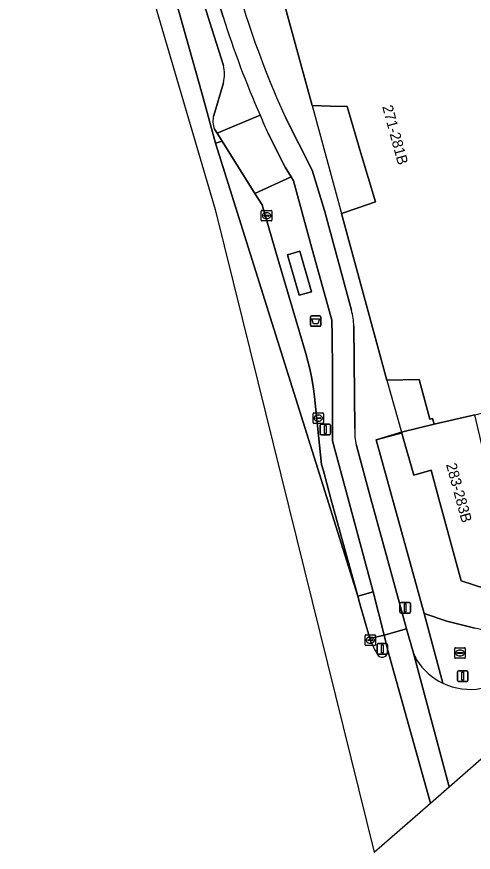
# Model space of a CAD drawing. Extents: x 162344 to 162869, y 381217 to 381818.
# Drawn here: x 162507.7 to 162551, y 381216.5 to 381295.7 of the extents above; entities that cross this region are included whole.
import ezdxf

# ---------------------------------------------------------------- set-up
doc = ezdxf.new("R2010")
doc.units = 0
for name, color, linetype in [('IMGEO_Afvalbak', 7, 'Continuous'), ('IMGEO_Berm_open', 7, 'Continuous'), ('IMGEO_Brandkraan', 7, 'Continuous'), ('IMGEO_Erf', 7, 'Continuous'), ('IMGEO_Fietspad_gesloten', 7, 'Continuous'), ('IMGEO_Fietspad_open', 7, 'Continuous'), ('IMGEO_Kolk', 7, 'Continuous'), ('IMGEO_Lichtmast', 7, 'Continuous'), ('IMGEO_Muur', 7, 'Continuous'), ('IMGEO_OVBaan_gesloten', 7, 'Continuous'), ('IMGEO_Pand', 7, 'Continuous'), ('IMGEO_Pand_nummerreeks', 7, 'Continuous'), ('IMGEO_Pand_overbouw', 7, 'Continuous'), ('IMGEO_Parkeervlak_open', 7, 'Continuous'), ('IMGEO_Rijbaan_lokaal_gesloten', 7, 'Continuous'), ('IMGEO_Rijbaan_regionaal_gesloten', 7, 'Continuous'), ('IMGEO_Verkeerseiland_open', 7, 'Continuous'), ('IMGEO_Verkeersregelinstallatiepaal', 7, 'Continuous'), ('IMGEO_Voetpad_gesloten', 7, 'Continuous'), ('IMGEO_Voetpad_open', 7, 'Continuous')]:
    doc.layers.add(name, color=color, linetype=linetype)

msp = doc.modelspace()

# ---------------------------------------------------------------- linework, layer by layer
at = {"layer": 'IMGEO_Afvalbak'}
for p, q in [((162535.561, 381266.45), (162535.561, 381267.25)), ((162535.561, 381267.25), (162535.561, 381266.45)), ((162535.661, 381267.35), (162536.451, 381267.35)), ((162536.451, 381267.35), (162535.661, 381267.35)), ((162536.551, 381267.25), (162536.551, 381266.45)), ((162536.551, 381266.45), (162536.551, 381267.25)), ((162536.451, 381266.35), (162535.661, 381266.35)), ((162535.661, 381266.35), (162536.451, 381266.35))]:
    msp.add_line(p, q, dxfattribs=at)
msp.add_lwpolyline([(162535.704, 381267.064), (162536.408, 381267.064), (162536.259, 381266.594), (162535.853, 381266.594), (162535.704, 381267.064)], dxfattribs=at)
for centre, start, end in [((162535.661, 381267.25), 90, 180), ((162535.661, 381267.25), 90, 180), ((162536.451, 381267.25), 0, 90), ((162536.451, 381267.25), 360, 90), ((162535.661, 381266.45), 180, 270), ((162535.661, 381266.45), 180, 270), ((162536.451, 381266.45), 270, 0), ((162536.451, 381266.45), 270, 0)]:
    msp.add_arc(centre, 0.1, start, end, dxfattribs=at)
at = {"layer": 'IMGEO_Berm_open'}
for points in [[(162510.574, 381341.66), (162511.386, 381341.368), (162511.659, 381341.199), (162511.867, 381340.946), (162512.219, 381340.273), (162517.818, 381322.123), (162520.103, 381314.39), (162520.562, 381312.814), (162522.874, 381305.299), (162525.989, 381295.243), (162527.307, 381291.065)], [(162527.279, 381295.674), (162524.133, 381305.697), (162521.857, 381313.223), (162521.427, 381314.724)], [(162527.313, 381289.434), (162526.386, 381286.339)], [(162526.464, 381285.037), (162526.715, 381284.645), (162530.786, 381286.346)], [(162530.786, 381286.346), (162526.715, 381284.645), (162527.18, 381283.901), (162530.281, 381278.934), (162533.735, 381280.515), (162533.169, 381281.443), (162531.534, 381284.676)]]:
    msp.add_lwpolyline(points, dxfattribs=at)
for points in [[(162537.654, 381255.503), (162537.645, 381262.173), (162537.64, 381265.461), (162537.595, 381266.931), (162535.6, 381274.097), (162533.967, 381280.135), (162533.735, 381280.515), (162530.281, 381278.934), (162530.988, 381277.853), (162532.465, 381272.733), (162535.121, 381263.759), (162535.505, 381262.307), (162535.632, 381261.729), (162535.653, 381261.609), (162535.857, 381260.414), (162535.952, 381259.66), (162536.619, 381253.257), (162536.79, 381252.665), (162537.51, 381250), (162538.37, 381246.814), (162540.052, 381240.792), (162541.522, 381241.189), (162539.141, 381250)], [(162534.488, 381269.288), (162533.382, 381273.13), (162534.57, 381273.472), (162535.675, 381269.629)]]:
    msp.add_lwpolyline(points, close=True, dxfattribs=at)
for centre, radius, start, end in [((162618.741, 381324.737), 95.969, 197.62834, 203.58065), ((162524.395, 381290.239), 3.027, 344.58062, 15.84093), ((162528.312, 381285.801), 2, 164.39587, 202.46086), ((162616.65, 381323.802), 93.678, 203.5682, 204.68741)]:
    msp.add_arc(centre, radius, start, end, dxfattribs=at)
at = {"layer": 'IMGEO_Brandkraan'}
for p, q in [((162549.25, 381234.966), (162549.25, 381235.818)), ((162549.325, 381235.892), (162550.177, 381235.892)), ((162549.509, 381235.386), (162549.509, 381235.398)), ((162549.947, 381235.349), (162549.549, 381235.349)), ((162549.552, 381235.435), (162549.95, 381235.435)), ((162549.738, 381235.672), (162549.763, 381235.672)), ((162549.993, 381235.398), (162549.993, 381235.386)), ((162550.251, 381235.818), (162550.251, 381234.966)), ((162550.177, 381234.892), (162549.325, 381234.892)), ((162549.761, 381235.112), (162549.736, 381235.112))]:
    msp.add_line(p, q, dxfattribs=at)
for points in [[(162549.25, 381234.966), (162549.25, 381235.818)], [(162549.325, 381235.892), (162550.177, 381235.892)], [(162550.251, 381235.818), (162550.251, 381234.966)], [(162550.177, 381234.892), (162549.325, 381234.892)]]:
    msp.add_lwpolyline(points, dxfattribs=at)
for centre, radius, start, end in [((162549.327, 381235.816), 0.0765, 91.55205, 178.44795), ((162549.327, 381235.816), 0.0765, 91.55205, 178.44795), ((162549.549, 381235.395), 0.0403, 85.87752, 175.75265), ((162549.546, 381235.385), 0.0366, 178.93798, 274.71019), ((162549.95, 381235.392), 0.043, 264.86636, 352.45326), ((162549.954, 381235.397), 0.0386, 1.73085, 96.63898), ((162550.175, 381235.816), 0.0765, 1.55205, 88.44795), ((162550.175, 381235.816), 0.0765, 1.55205, 88.44795), ((162549.327, 381234.968), 0.0765, 181.55205, 268.44795), ((162549.327, 381234.968), 0.0765, 181.55205, 268.44795), ((162550.175, 381234.968), 0.0765, 271.55205, 358.44795), ((162550.175, 381234.968), 0.0765, 271.55205, 358.44795)]:
    msp.add_arc(centre, radius, start, end, dxfattribs=at)
for centre, major_axis, ratio, start_param, end_param in [((162549.737, 381235.392), (-0.387, 0.002), 0.722429, 4.712389, 7.853982), ((162549.762, 381235.392), (-0.39, 0.002), 0.717154, 1.570796, 4.712389)]:
    msp.add_ellipse(centre, major_axis=major_axis, ratio=ratio, start_param=start_param, end_param=end_param, dxfattribs=at)
at = {"layer": 'IMGEO_Erf'}
msp.add_lwpolyline([(162552.202, 381241.487), (162549.873, 381242.23), (162547.75, 381250), (162547.01, 381252.709), (162545.366, 381252.259), (162544.188, 381256.303), (162541.807, 381255.586), (162546.357, 381239.143), (162548.502, 381238.42), (162551.16, 381237.735)], dxfattribs=at)
at = {"layer": 'IMGEO_Fietspad_gesloten'}
msp.add_lwpolyline([(162546.96, 381221.17), (162548.732, 381222.717), (162545.325, 381235.375), (162544.688, 381237.687), (162542.542, 381237.097), (162542.916, 381235.613), (162546.96, 381221.17)], dxfattribs=at)
at = {"layer": 'IMGEO_Fietspad_open'}
for points in [[(162517.652, 381327.383), (162519.119, 381322.49), (162521.427, 381314.724), (162521.857, 381313.223), (162524.133, 381305.697), (162527.279, 381295.674)], [(162539.452, 381267.881), (162536.892, 381277.328), (162535.741, 381281.143), (162533.191, 381286.14)], [(162531.534, 381284.676), (162533.169, 381281.443), (162533.735, 381280.515), (162533.967, 381280.135), (162535.6, 381274.097), (162537.595, 381266.931), (162537.64, 381265.461), (162537.645, 381262.173), (162537.654, 381255.503), (162539.141, 381250), (162541.522, 381241.189), (162542.542, 381237.097), (162544.688, 381237.687), (162542.892, 381244.154), (162541.306, 381250), (162539.931, 381255.067)], [(162539.767, 381256.636), (162539.669, 381266.348)]]:
    msp.add_lwpolyline(points, dxfattribs=at)
for centre, radius, start, end in [((162618.146, 381324.632), 93.268, 197.57252, 204.37463), ((162618.741, 381324.737), 95.969, 197.62834, 203.58065), ((162616.65, 381323.802), 93.678, 203.5682, 204.68741), ((162534.192, 381266.355), 5.477, 359.93048, 16.18319), ((162545.032, 381256.393), 5.271, 177.36027, 194.5741)]:
    msp.add_arc(centre, radius, start, end, dxfattribs=at)
at = {"layer": 'IMGEO_Kolk'}
for p, q in [((162530.903, 381276.41), (162530.903, 381277.262)), ((162530.978, 381277.336), (162531.83, 381277.336)), ((162531.904, 381277.262), (162531.904, 381276.41)), ((162531.162, 381276.83), (162531.162, 381276.842)), ((162531.6, 381276.793), (162531.202, 381276.793)), ((162531.205, 381276.879), (162531.603, 381276.879)), ((162531.414, 381276.556), (162531.389, 381276.556)), ((162531.391, 381277.116), (162531.416, 381277.116)), ((162531.646, 381276.842), (162531.646, 381276.83)), ((162531.83, 381276.336), (162530.978, 381276.336)), ((162535.809, 381257.219), (162535.809, 381258.071)), ((162535.884, 381258.145), (162536.736, 381258.145)), ((162536.068, 381257.639), (162536.068, 381257.651)), ((162536.506, 381257.602), (162536.108, 381257.602)), ((162536.111, 381257.688), (162536.509, 381257.688)), ((162536.297, 381257.925), (162536.322, 381257.925)), ((162536.552, 381257.651), (162536.552, 381257.639)), ((162536.81, 381258.071), (162536.81, 381257.219)), ((162536.736, 381257.145), (162535.884, 381257.145)), ((162536.32, 381257.365), (162536.295, 381257.365)), ((162540.742, 381236.18), (162540.742, 381237.032)), ((162540.817, 381237.106), (162541.669, 381237.106)), ((162541.23, 381236.886), (162541.255, 381236.886)), ((162541.743, 381237.032), (162541.743, 381236.18)), ((162541.669, 381236.106), (162540.817, 381236.106)), ((162541.001, 381236.6), (162541.001, 381236.612)), ((162541.439, 381236.563), (162541.041, 381236.563)), ((162541.044, 381236.649), (162541.442, 381236.649)), ((162541.253, 381236.326), (162541.228, 381236.326)), ((162541.485, 381236.612), (162541.485, 381236.6))]:
    msp.add_line(p, q, dxfattribs=at)
for points in [[(162530.903, 381276.41), (162530.903, 381277.262)], [(162530.978, 381277.336), (162531.83, 381277.336)], [(162531.904, 381277.262), (162531.904, 381276.41)], [(162531.83, 381276.336), (162530.978, 381276.336)], [(162535.809, 381257.219), (162535.809, 381258.071)], [(162535.884, 381258.145), (162536.736, 381258.145)], [(162536.81, 381258.071), (162536.81, 381257.219)], [(162536.736, 381257.145), (162535.884, 381257.145)], [(162540.742, 381236.18), (162540.742, 381237.032)], [(162540.817, 381237.106), (162541.669, 381237.106)], [(162541.743, 381237.032), (162541.743, 381236.18)], [(162541.669, 381236.106), (162540.817, 381236.106)]]:
    msp.add_lwpolyline(points, dxfattribs=at)
for centre, radius, start, end in [((162530.98, 381277.26), 0.0765, 91.55205, 178.44795), ((162530.98, 381277.26), 0.0765, 91.55205, 178.44795), ((162531.828, 381277.26), 0.0765, 1.55205, 88.44795), ((162531.828, 381277.26), 0.0765, 1.55205, 88.44795), ((162531.202, 381276.839), 0.0403, 85.87752, 175.75265), ((162531.199, 381276.829), 0.0366, 178.93798, 274.71019), ((162531.603, 381276.836), 0.043, 264.86636, 352.45326), ((162531.607, 381276.841), 0.0386, 1.73085, 96.63898), ((162530.98, 381276.412), 0.0765, 181.55205, 268.44795), ((162530.98, 381276.412), 0.0765, 181.55205, 268.44795), ((162531.828, 381276.412), 0.0765, 271.55205, 358.44795), ((162531.828, 381276.412), 0.0765, 271.55205, 358.44795), ((162535.886, 381258.069), 0.0765, 91.55205, 178.44795), ((162535.886, 381258.069), 0.0765, 91.55205, 178.44795), ((162536.108, 381257.648), 0.0403, 85.87752, 175.75265), ((162536.105, 381257.638), 0.0366, 178.93798, 274.71019), ((162536.509, 381257.645), 0.043, 264.86636, 352.45326), ((162536.513, 381257.65), 0.0386, 1.73085, 96.63898), ((162536.734, 381258.069), 0.0765, 1.55205, 88.44795), ((162536.734, 381258.069), 0.0765, 1.55205, 88.44795), ((162535.886, 381257.221), 0.0765, 181.55205, 268.44795), ((162535.886, 381257.221), 0.0765, 181.55205, 268.44795), ((162536.734, 381257.221), 0.0765, 271.55205, 358.44795), ((162536.734, 381257.221), 0.0765, 271.55205, 358.44795), ((162540.819, 381237.03), 0.0765, 91.55205, 178.44795), ((162540.819, 381237.03), 0.0765, 91.55205, 178.44795), ((162541.667, 381237.03), 0.0765, 1.55205, 88.44795), ((162541.667, 381237.03), 0.0765, 1.55205, 88.44795), ((162540.819, 381236.182), 0.0765, 181.55205, 268.44795), ((162540.819, 381236.182), 0.0765, 181.55205, 268.44795), ((162541.041, 381236.609), 0.0403, 85.87752, 175.75265), ((162541.038, 381236.599), 0.0366, 178.93798, 274.71019), ((162541.442, 381236.606), 0.043, 264.86636, 352.45326), ((162541.446, 381236.611), 0.0386, 1.73085, 96.63898), ((162541.667, 381236.182), 0.0765, 271.55205, 358.44795), ((162541.667, 381236.182), 0.0765, 271.55205, 358.44795)]:
    msp.add_arc(centre, radius, start, end, dxfattribs=at)
for centre, major_axis, ratio, start_param, end_param in [((162531.39, 381276.836), (-0.387, 0.002), 0.722429, 4.712389, 7.853982), ((162531.415, 381276.836), (-0.39, 0.002), 0.717154, 1.570796, 4.712389), ((162536.296, 381257.645), (-0.387, 0.002), 0.722429, 4.712389, 7.853982), ((162536.321, 381257.645), (-0.39, 0.002), 0.717154, 1.570796, 4.712389), ((162541.229, 381236.606), (-0.387, 0.002), 0.722429, 4.712389, 7.853982), ((162541.254, 381236.606), (-0.39, 0.002), 0.717154, 1.570796, 4.712389)]:
    msp.add_ellipse(centre, major_axis=major_axis, ratio=ratio, start_param=start_param, end_param=end_param, dxfattribs=at)
at = {"layer": 'IMGEO_Lichtmast'}
for p, q in [((162536.473, 381256.178), (162536.473, 381256.978)), ((162536.473, 381256.978), (162536.473, 381256.178)), ((162536.573, 381257.078), (162537.363, 381257.078)), ((162537.363, 381257.078), (162536.573, 381257.078)), ((162537.463, 381256.978), (162537.463, 381256.178)), ((162537.463, 381256.178), (162537.463, 381256.978)), ((162537.363, 381256.078), (162536.573, 381256.078)), ((162536.573, 381256.078), (162537.363, 381256.078))]:
    msp.add_line(p, q, dxfattribs=at)
msp.add_lwpolyline([(162536.893, 381256.953), (162537.043, 381256.953), (162537.043, 381256.203), (162536.893, 381256.203), (162536.893, 381256.953)], dxfattribs=at)
for centre, start, end in [((162536.573, 381256.978), 90, 180), ((162536.573, 381256.978), 90, 180), ((162537.363, 381256.978), 0, 90), ((162537.363, 381256.978), 360, 90), ((162536.573, 381256.178), 180, 270), ((162536.573, 381256.178), 180, 270), ((162537.363, 381256.178), 270, 0), ((162537.363, 381256.178), 270, 0)]:
    msp.add_arc(centre, 0.1, start, end, dxfattribs=at)
at = {"layer": 'IMGEO_Muur'}
msp.add_lwpolyline([(162548.502, 381238.42), (162546.357, 381239.143), (162541.807, 381255.586), (162544.277, 381256.243)], dxfattribs=at)
at = {"layer": 'IMGEO_OVBaan_gesloten'}
msp.add_lwpolyline([(162530.988, 381277.853), (162530.281, 381278.934), (162527.18, 381283.901), (162526.558, 381283.713), (162526.561, 381283.703), (162540.052, 381240.792), (162538.37, 381246.814), (162537.51, 381250), (162536.79, 381252.665), (162536.619, 381253.257), (162535.952, 381259.66), (162535.857, 381260.414), (162535.653, 381261.609), (162535.632, 381261.729), (162535.505, 381262.307), (162535.121, 381263.759), (162532.465, 381272.733)], close=True, dxfattribs=at)
at = {"layer": 'IMGEO_Pand'}
msp.add_lwpolyline([(162532.111, 381300.452), (162535.716, 381287.283), (162537.474, 381287.222), (162539.054, 381287.166), (162540.356, 381282.758), (162541.72, 381278.142), (162540.106, 381277.587), (162538.509, 381277.038), (162542.805, 381261.237), (162545.864, 381261.323), (162546.898, 381257.547), (162547.034, 381257.585), (162547.156, 381257.619), (162547.217, 381257.396), (162547.306, 381257.072), (162551.147, 381257.961), (162552.843, 381258.364), (162556.091, 381261.43), (162554.642, 381267.538), (162554.115, 381269.762), (162566.707, 381281.647), (162566.923, 381281.851), (162589.686, 381303.335)], dxfattribs=at)
msp.add_lwpolyline([(162557.571, 381253.688), (162557.396, 381253.523), (162556.971, 381253.975), (162555.196, 381255.827), (162551.85, 381254.998), (162551.147, 381257.961), (162547.306, 381257.072), (162544.188, 381256.303), (162545.366, 381252.259), (162547.01, 381252.709), (162547.75, 381250), (162549.873, 381242.23), (162552.202, 381241.487), (162559.813, 381248.655), (162559.251, 381249.252), (162560.044, 381250), (162560.399, 381250.335), (162560.546, 381250.474)], close=True, dxfattribs=at)
at = {"layer": 'IMGEO_Pand_overbouw'}
for points in [[(162535.716, 381287.283), (162538.509, 381277.038), (162540.106, 381277.587), (162541.72, 381278.142), (162540.356, 381282.758), (162539.054, 381287.166), (162537.474, 381287.222)], [(162542.805, 381261.237), (162544.188, 381256.303), (162547.306, 381257.072), (162547.217, 381257.396), (162547.156, 381257.619), (162547.034, 381257.585), (162546.898, 381257.547), (162545.864, 381261.323)]]:
    msp.add_lwpolyline(points, close=True, dxfattribs=at)
at = {"layer": 'IMGEO_Parkeervlak_open'}
for points in [[(162508.55, 381344.901), (162508.674, 381344.38), (162513.331, 381329.554), (162517.911, 381314.419), (162522.207, 381299.376), (162525.308, 381288.359), (162526.558, 381283.713), (162527.18, 381283.901), (162526.715, 381284.645), (162526.464, 381285.037)], [(162527.307, 381291.065), (162525.989, 381295.243), (162522.874, 381305.299), (162520.562, 381312.814), (162520.103, 381314.39), (162517.818, 381322.123)], [(162526.386, 381286.339), (162527.313, 381289.434)]]:
    msp.add_lwpolyline(points, dxfattribs=at)
for centre, radius, start, end in [((162524.395, 381290.239), 3.027, 344.58062, 15.84093), ((162528.312, 381285.801), 2, 164.39587, 202.46086)]:
    msp.add_arc(centre, radius, start, end, dxfattribs=at)
at = {"layer": 'IMGEO_Rijbaan_lokaal_gesloten'}
for points in [[(162548.732, 381222.717), (162560.587, 381233.07), (162563.203, 381235.53), (162562.264, 381236.529)], [(162545.325, 381235.375), (162548.732, 381222.717)]]:
    msp.add_lwpolyline(points, dxfattribs=at)
for centre, radius, start, end in [((162548.803, 381236.696), 3.721, 200.79618, 211.68037), ((162550.711, 381237.955), 6.006, 212.34318, 244.48419), ((162550.721, 381237.962), 6.016, 244.4293, 280.31604)]:
    msp.add_arc(centre, radius, start, end, dxfattribs=at)
at = {"layer": 'IMGEO_Rijbaan_regionaal_gesloten'}
for points in [[(162502.425, 381364.362), (162500.079, 381370.136), (162500, 381370.319), (162496.843, 381377.63), (162494.655, 381382.362), (162493.023, 381385.688), (162491.272, 381389.216), (162490.627, 381390.497), (162489.821, 381392.102), (162487.336, 381390.854), (162495.049, 381375.437), (162501.803, 381357.869), (162506.293, 381346.192), (162526.533, 381277.419), (162529.09, 381267.097), (162541.62, 381216.506)], [(162541.186, 381236.755), (162540.257, 381240.057), (162540.052, 381240.792), (162526.561, 381283.703), (162526.558, 381283.713), (162525.308, 381288.359), (162522.207, 381299.376), (162517.911, 381314.419), (162513.331, 381329.554), (162508.674, 381344.38), (162508.55, 381344.901)], [(162541.62, 381216.506), (162546.96, 381221.17), (162542.916, 381235.613)]]:
    msp.add_lwpolyline(points, dxfattribs=at)
for centre, radius, start, end in [((162547.984, 381239.164), 7.212, 199.51241, 213.78924), ((162542.37, 381235.551), 0.55, 226.31867, 6.51405)]:
    msp.add_arc(centre, radius, start, end, dxfattribs=at)
at = {"layer": 'IMGEO_Verkeerseiland_open'}
for points in [[(162542.542, 381237.097), (162541.186, 381236.755)], [(162542.916, 381235.613), (162542.542, 381237.097)]]:
    msp.add_lwpolyline(points, dxfattribs=at)
for centre, radius, start, end in [((162547.984, 381239.164), 7.212, 199.51241, 213.78924), ((162542.37, 381235.551), 0.55, 226.31867, 6.51405)]:
    msp.add_arc(centre, radius, start, end, dxfattribs=at)
at = {"layer": 'IMGEO_Verkeersregelinstallatiepaal'}
for p, q in [((162544.056, 381239.279), (162544.056, 381240.079)), ((162544.056, 381240.079), (162544.056, 381239.279)), ((162544.156, 381240.179), (162544.946, 381240.179)), ((162544.946, 381240.179), (162544.156, 381240.179)), ((162545.046, 381240.079), (162545.046, 381239.279)), ((162545.046, 381239.279), (162545.046, 381240.079)), ((162544.946, 381239.179), (162544.156, 381239.179)), ((162544.156, 381239.179), (162544.946, 381239.179)), ((162541.889, 381235.377), (162541.889, 381236.177)), ((162541.889, 381236.177), (162541.889, 381235.377)), ((162541.989, 381236.277), (162542.779, 381236.277)), ((162542.779, 381236.277), (162541.989, 381236.277)), ((162542.879, 381236.177), (162542.879, 381235.377)), ((162542.879, 381235.377), (162542.879, 381236.177)), ((162542.779, 381235.277), (162541.989, 381235.277)), ((162541.989, 381235.277), (162542.779, 381235.277)), ((162549.615, 381233.701), (162550.405, 381233.701)), ((162550.405, 381233.701), (162549.615, 381233.701)), ((162549.515, 381232.801), (162549.515, 381233.601)), ((162549.515, 381233.601), (162549.515, 381232.801)), ((162550.505, 381233.601), (162550.505, 381232.801)), ((162550.505, 381232.801), (162550.505, 381233.601)), ((162550.405, 381232.701), (162549.615, 381232.701)), ((162549.615, 381232.701), (162550.405, 381232.701))]:
    msp.add_line(p, q, dxfattribs=at)
for points in [[(162544.476, 381240.054), (162544.626, 381240.054), (162544.626, 381239.304), (162544.476, 381239.304), (162544.476, 381240.054)], [(162542.309, 381236.152), (162542.459, 381236.152), (162542.459, 381235.402), (162542.309, 381235.402), (162542.309, 381236.152)], [(162549.935, 381233.576), (162550.085, 381233.576), (162550.085, 381232.826), (162549.935, 381232.826), (162549.935, 381233.576)]]:
    msp.add_lwpolyline(points, dxfattribs=at)
for centre, start, end in [((162544.156, 381240.079), 90, 180), ((162544.156, 381240.079), 90, 180), ((162544.946, 381240.079), 0, 90), ((162544.946, 381240.079), 360, 90), ((162544.156, 381239.279), 180, 270), ((162544.156, 381239.279), 180, 270), ((162544.946, 381239.279), 270, 0), ((162544.946, 381239.279), 270, 0), ((162541.989, 381236.177), 90, 180), ((162541.989, 381236.177), 90, 180), ((162542.779, 381236.177), 0, 90), ((162542.779, 381236.177), 360, 90), ((162541.989, 381235.377), 180, 270), ((162541.989, 381235.377), 180, 270), ((162542.779, 381235.377), 270, 0), ((162542.779, 381235.377), 270, 0), ((162549.615, 381233.601), 90, 180), ((162549.615, 381233.601), 90, 180), ((162550.405, 381233.601), 0, 90), ((162550.405, 381233.601), 360, 90), ((162549.615, 381232.801), 180, 270), ((162549.615, 381232.801), 180, 270), ((162550.405, 381232.801), 270, 0), ((162550.405, 381232.801), 270, 0)]:
    msp.add_arc(centre, 0.1, start, end, dxfattribs=at)
at = {"layer": 'IMGEO_Voetpad_gesloten'}
msp.add_lwpolyline([(162534.57, 381273.472), (162533.382, 381273.13), (162534.488, 381269.288), (162535.675, 381269.629)], close=True, dxfattribs=at)
at = {"layer": 'IMGEO_Voetpad_open'}
for points in [[(162653.53, 381330.558), (162653.265, 381330.852), (162649.241, 381327.313), (162606.75, 381287.36), (162605.911, 381286.571), (162553.447, 381237.241), (162551.16, 381237.735), (162548.502, 381238.42), (162546.357, 381239.143), (162548.124, 381232.535)], [(162548.124, 381232.535), (162546.357, 381239.143), (162541.807, 381255.586), (162544.188, 381256.303), (162547.306, 381257.072), (162547.217, 381257.396), (162547.156, 381257.619), (162547.034, 381257.585), (162546.898, 381257.547), (162545.864, 381261.323), (162542.805, 381261.237), (162538.509, 381277.038), (162540.106, 381277.587), (162541.72, 381278.142), (162540.356, 381282.758), (162539.054, 381287.166), (162537.474, 381287.222), (162535.716, 381287.283), (162532.111, 381300.452), (162538.981, 381304.149)], [(162533.191, 381286.14), (162535.741, 381281.143), (162536.892, 381277.328), (162539.452, 381267.881)], [(162539.669, 381266.348), (162539.767, 381256.636)], [(162539.931, 381255.067), (162541.306, 381250), (162542.892, 381244.154), (162544.688, 381237.687), (162545.325, 381235.375)]]:
    msp.add_lwpolyline(points, dxfattribs=at)
msp.add_lwpolyline([(162541.522, 381241.189), (162540.052, 381240.792), (162540.257, 381240.057), (162541.186, 381236.755), (162542.542, 381237.097)], close=True, dxfattribs=at)
for centre, radius, start, end in [((162618.146, 381324.632), 93.268, 197.57252, 204.37463), ((162534.192, 381266.355), 5.477, 359.93048, 16.18319), ((162545.032, 381256.393), 5.271, 177.36027, 194.5741), ((162548.803, 381236.696), 3.721, 200.79618, 211.68037), ((162550.711, 381237.955), 6.006, 212.34318, 244.48419), ((162550.721, 381237.962), 6.016, 244.4293, 280.31604)]:
    msp.add_arc(centre, radius, start, end, dxfattribs=at)

# ---------------------------------------------------------------- texts
at = {"layer": 'IMGEO_Pand_nummerreeks'}
for s, rotation, p in [('271-281B', 285.31495, (162542.361, 381287.165)), ('283-283B', 285.28057, (162548.417, 381253.248))]:
    msp.add_text(s, height=1, rotation=rotation, dxfattribs=at).set_placement(p)

doc.saveas('drawing.dxf')
